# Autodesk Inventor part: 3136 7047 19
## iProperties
Shininess: 25.0
Length Units: 11269
Angle Units: 11279
Time Units: 11290
Mass Units: 11283
Length Display Precision: 3
Angle Display Precision: 2
Compacted: True
Created: 2001-04
Part Number: 3136 7047 19
Material: Steel, Mild
Document SubType Name: Modeling
Designer: Joe M
Description: Clamp
Engineer: Joe M
Density: 7.86
Volumn: 100.00000000000003
Area: 240.00000000000006
PropertySet Name: Model Information
Control State: 0
Master: False
Checked Out: False
Last Check In Date: 2001-04-09
Last Check In By: brpog
Title: Klammer
Author: Joe M
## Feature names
1. Extrusion2
2. Extrusion3
3. Extrusion4
4. Extrusion6
5. Sweep1
